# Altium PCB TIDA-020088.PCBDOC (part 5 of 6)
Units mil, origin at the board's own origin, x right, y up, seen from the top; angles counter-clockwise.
Board outline 7520.69 x 5119.11 mil, 6 copper layers (TOP, GND02, SIG03, SIG04, GND05, BOTTOM), stack 87.024 mil thick; 539 components, 269 nets, 1479 pads, 2085 vias.
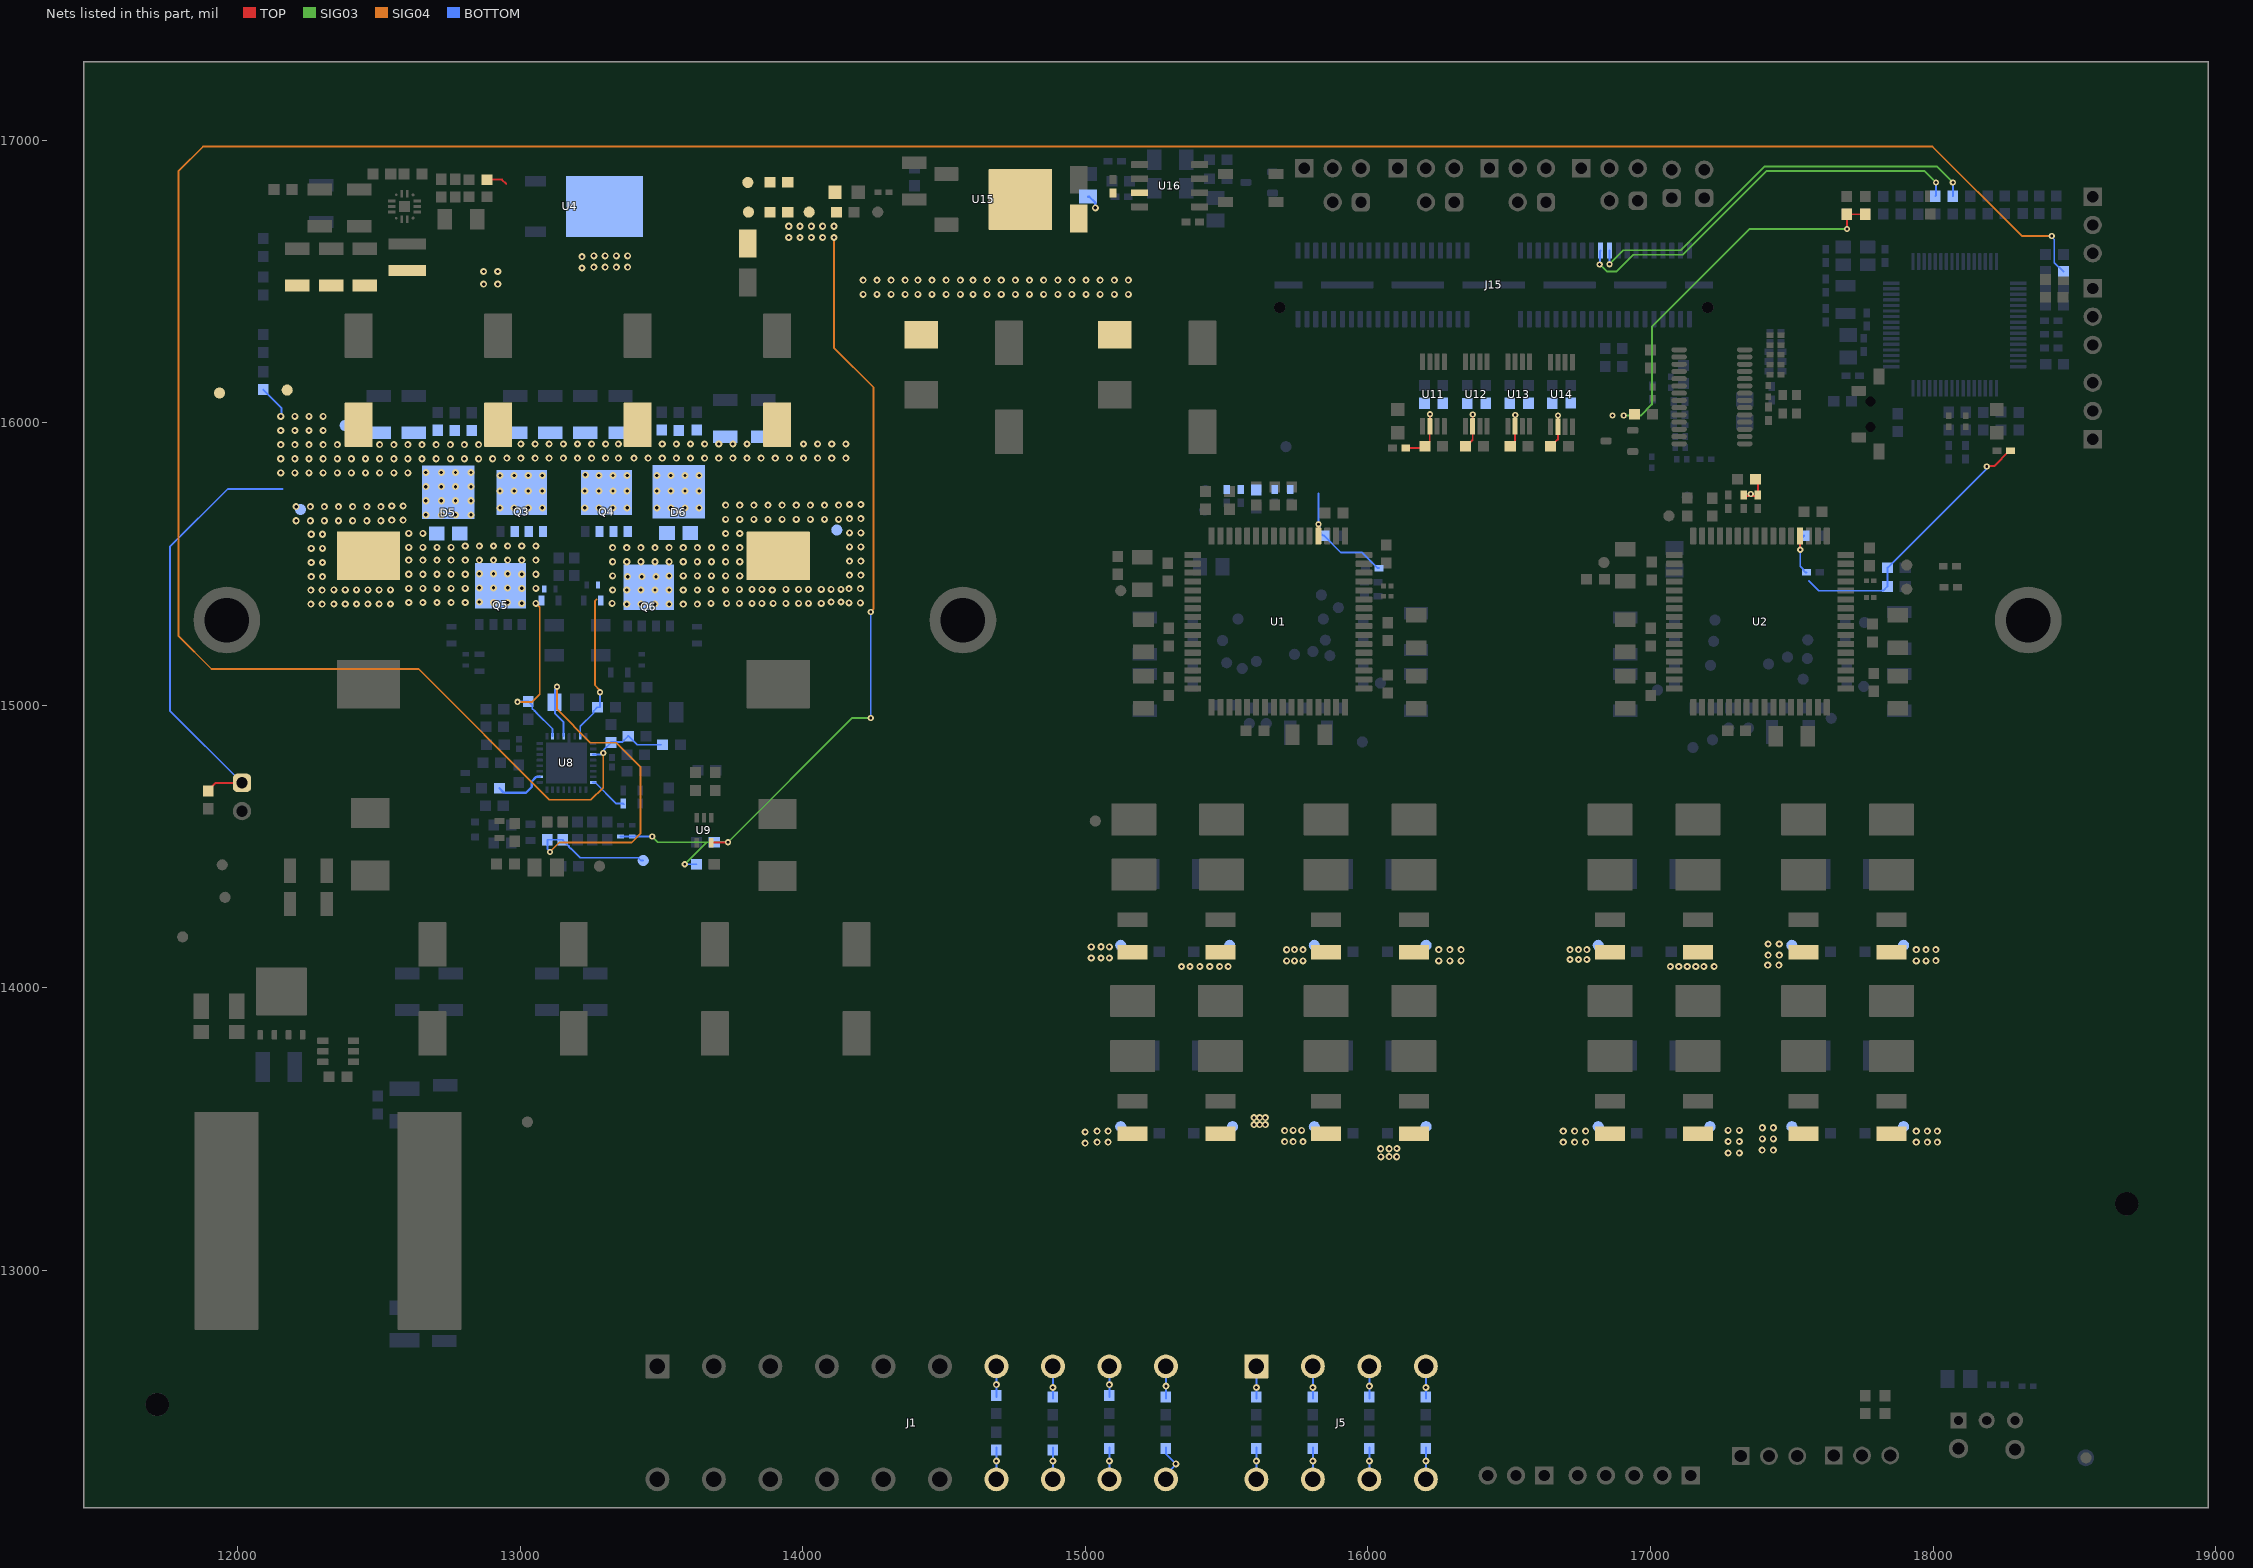
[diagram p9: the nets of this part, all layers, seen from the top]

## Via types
v1: diameter 25, hole 12, TOP to BOTTOM, tented both sides, 1621 vias
v2: diameter 22, hole 10, TOP to BOTTOM, tented both sides, 436 vias
v3: diameter 236.22, hole 137.8, TOP to BOTTOM, 15 vias
v4: diameter 19.68, hole 7.87, TOP to BOTTOM, tented both sides, 12 vias
v5: diameter 19.68, hole 7.87, TOP to BOTTOM, 1 vias

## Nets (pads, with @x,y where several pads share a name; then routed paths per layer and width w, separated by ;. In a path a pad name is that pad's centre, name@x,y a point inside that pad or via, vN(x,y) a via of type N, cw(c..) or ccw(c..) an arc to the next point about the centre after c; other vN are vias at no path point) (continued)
SPK_OUT1+: C23.1 C27.1 J1.14 R2.2 TP8.1 | length 113.4
  BOTTOM w6.5: J1.14@14685,12260 v1(14685,12325) C27.1@14685,12373.43
  other v1: 15596.62,13515.39 15616.62,13515.39 15636.62,13515.39 15596.62,13540.39 15616.62,13540.39 15636.62,13540.39
SPK_OUT1-: C24.1 C28.1 J1.13 R4.2 TP10.1 | length 113.4
  BOTTOM w6.5: C28.1@14685,12551.57 v1(14685,12595) ; v1@14685,12590 J1.13@14685,12660
  other v1: 14999.23,13449.87 15041.24,13453.2 15080.61,13453.2 14999.23,13489.24 15041.24,13492.57 15080.61,13492.57
SPK_OUT2+: C31.1 C35.1 J1.16 R8.2 TP14.1 | length 113.4
  BOTTOM w6.5: J1.16@14885,12260 v1(14885,12325) C35.1@14885,12373.43
  other v1: 15340,14075 15370,14075 15405,14075 15440,14075 15475,14075 15505,14075
SPK_OUT2-: C32.1 C36.1 J1.15 R10.2 TP16.1 | length 113.4
  BOTTOM w6.5: C36.1@14885,12546.57 v1(14885,12585) J1.15@14885,12660
  other v1: 15020.63,14105 15055,14105 15085,14105 15020.63,14144.37 15085,14144.37 15055,14145
SPK_OUT3+: C39.1 C43.1 J1.18 R12.2 TP20.1 | length 113.4
  BOTTOM w6.5: J1.18@15085,12260 v1(15085,12325) C43.1@15085,12373.43
  other v1: 16250.61,14095.2 16289.98,14095.2 16329.98,14095.2 16250.61,14134.57 16289.98,14134.57 16329.98,14134.57
SPK_OUT3-: C40.1 C44.1 J1.17 R13.2 TP22.1 | length 113.4
  BOTTOM w6.5: C44.1@15085,12551.57 v1(15085,12595) ; v1@15085,12590 J1.17@15085,12660
  other v1: 15712.14,14094.9 15740,14095 15770,14095 15712.14,14134.27 15740,14135 15770,14135
SPK_OUT4+: C47.1 C51.1 J1.20 R14.2 TP26.1 | length 142.4
  BOTTOM w6.5: J1.20@15285,12260 15285,12275.94 15320,12310.94 v1(15320,12315) 15285,12350 C51.1@15285,12373.43
  other v1: 16045.69,13401.25 16074.71,13402 16101.74,13401.75 16045,13430 16075,13430 16101.99,13431.02
SPK_OUT4-: C48.1 C52.1 J1.19 R17.2 TP28.1 | length 113.4
  BOTTOM w6.5: C52.1@15285,12546.57 v1(15285,12590) J1.19@15285,12660
  other v1: 15705,13455 15735,13455 15770,13455 15705,13494.37 15735,13495 15765,13495
SPK_OUT5+: C75.1 C79.1 J5.2 R21.2 TP37.1 | length 113.4
  BOTTOM w6.5: J5.2@15605,12260 v1(15605,12325) C79.1@15605,12373.43
  other v1: 17275,13415 17314.37,13415 17275,13455.63 17314.37,13455.63 17275,13495 17314.37,13495
SPK_OUT5-: C76.1 C80.1 J5.1 R23.2 TP39.1 | length 113.4
  BOTTOM w6.5: C80.1@15605,12546.57 v1(15605,12585) J5.1@15605,12660
  other v1: 16691.24,13453.2 16731.24,13453.2 16770.61,13453.2 16691.24,13492.57 16731.24,13492.57 16770.61,13492.57
SPK_OUT6+: C83.1 C87.1 J5.4 R27.2 TP43.1 | length 113.4
  BOTTOM w6.5: J5.4@15805,12260 v1(15805,12325) C87.1@15805,12373.43
  other v1: 17070,14075 17100,14075 17130,14075 17160,14075 17189,14074.99 17225,14075
SPK_OUT6-: C84.1 C88.1 J5.3 R28.2 TP45.1 | length 113.4
  BOTTOM w6.5: C88.1@15805,12546.57 v1(15805,12585) J5.3@15805,12660
  other v1: 16715,14100 16745,14100 16775,14100 16715,14135 16745,14135 16775,14135
SPK_OUT7+: C91.1 C95.1 J5.6 R30.2 TP49.1 | length 113.4
  BOTTOM w6.5: J5.6@16005,12260 v1(16005,12325) C95.1@16005,12373.43
  other v1: 17940.61,14095.2 17975,14095 18010,14095.63 17940.61,14134.57 17975,14135 18010,14135
SPK_OUT7-: C92.1 C96.1 J5.5 R31.2 TP51.1 | length 113.4
  BOTTOM w6.5: C96.1@16005,12546.57 J5.5@16005,12660
  other v1: 16005,12590 17415,14080 17454.37,14080 17416.24,14115.2 17455.61,14115.2 17416.24,14154.57 17455.61,14154.57
SPK_OUT8+: C99.1 C103.1 J5.8 R32.2 TP55.1 | length 113.4
  BOTTOM w6.5: J5.8@16205,12260 v1(16205,12325) C103.1@16205,12373.43
  other v1: 17940.61,13453.2 17979.98,13453.2 18014.98,13453.2 17940.61,13492.57 17979.98,13492.57 18014.98,13492.57
SPK_OUT8-: C100.1 C104.1 J5.7 R33.2 TP57.1 | length 113.4
  BOTTOM w6.5: C104.1@16205,12546.57 v1(16205,12585) J5.7@16205,12660
  other v1: 17395,13425 17435,13425 17395.63,13465 17435,13465 17395.63,13504.37 17435,13504.37
SS: C195.1 U8.2 | length 184.1
  BOTTOM w8: C195.1@12926.16,14705.65 12940.86,14690.95 12945.58,14690.95 12946.53,14690 13020,14690 13040,14710 13040,14730 13055.5,14745.5 13067.75,14745.5 U8.2@13068.67,14746.42
SW1: C175.1 C179.1 D5.1 D5.2 L19.1 Q3.1 Q3.2 Q3.3 Q5.5 R75.1 TP79.1 U8.10 | length 601.3
  SIG04 w6.5: v2(12989.89,15011.7) 13041.7,15011.7 13069,15039 13069,15346 13065,15350
  BOTTOM w6.5: C179.1@13028.49,15013.2 13042.23,14999.45 13042.23,14987.77 13050.36,14979.64 13051.23,14979.64 13056.94,14973.93 13056.94,14973.06 13113.95,14916.05 U8.10@13113.95,14890.12
  BOTTOM w8: v2(12989.89,15011.7) 13026.99,15011.7 C179.1@13028.49,15013.2
  other v1: 12258.39,15357.32 12298.39,15357.32 12340.35,15357.95 12380.35,15357.95 12420.35,15357.95 12460.35,15357.95 12500.35,15357.95 12540.35,15357.95 13005,15360 13055,15360 12605.11,15363.31 12655.11,15363.31 12705.11,15363.31 12755.11,15363.31 12805.11,15363.31 12905.11,15363.31 12955.11,15363.31 12855,15365 12258.39,15407.32 12298.39,15407.32 12340.35,15407.95 12380.35,15407.95 12420.35,15407.95 12460.35,15407.95 12500.35,15407.95 12540.35,15407.95 12605.11,15413.31 12655.11,15413.31 12705.11,15413.31 12755.11,15413.31 12805.11,15413.31 13005.11,15413.31 13055.11,15413.31 12855,15415 12905,15415 12955,15415 12260,15455 12300,15455 12605.11,15463.31 12655.11,15463.31 12705.11,15463.31 12755.11,15463.31 12805.11,15463.31 13005.11,15463.31 13055.11,15463.31 12855,15465 12905,15465 12955,15465 12260,15505 12300,15505 12605.11,15513.31 12655.11,15513.31 12705.11,15513.31 12755.11,15513.31 12805.11,15513.31 12855.11,15513.31 12905.11,15513.31 12955.11,15513.31 13005.11,15513.31 13055.11,15513.31 12260,15555 12300,15555 12605.11,15558.31 12655.11,15558.31 12705.11,15558.31 12755.11,15558.31 12805.11,15563.31 12855.11,15563.31 12905.11,15563.31 12955.11,15563.31 13005.11,15563.31 13055.11,15563.31 12260,15605 12300,15605 12605.11,15608.31 12655.11,15608.31 12206.61,15652.68 12256.61,15652.68 12306.61,15652.68 12356.61,15652.68 12406.61,15652.68 12456.61,15652.68 12506.61,15652.68 12545,15655 12585,15655 12206.61,15702.68 12256.61,15702.68 12306.61,15702.68 12356.61,15702.68 12406.61,15702.68 12456.61,15702.68 12506.61,15702.68 12545,15705 12585,15705
SW2: C176.1 C180.2 D6.1 D6.2 L20.2 Q4.1 Q4.2 Q4.3 Q6.5 R76.1 TP80.1 U8.15 | length 529.6
  SIG04 w6.5: 13270,15375 13264.2,15369.2 13264.2,15071.16 13280.11,15055.25 13280.11,15047.83 v2(13282.41,15045.54)
  BOTTOM w6.5: U8.15@13212.45,14890.2 U8.15@13212.37,14890.12 13212.37,14925.38 13259.02,14972.04 13259.02,14979.14 13272.72,14992.84 C180.2@13273.71,14992.84 13282.41,14992.84 v2(13282.41,15045.54)
  other v1: 13376.61,15357.68 13426.61,15357.68 13476.61,15357.68 13526.61,15357.68 13576.61,15357.68 13626.61,15357.68 13325,15360 13675,15360 13730,15360 13775,15360 13820,15360 13855,15360 13895,15360 13940,15360 13985,15360 14020,15360 14065,15360 14163.39,15362.32 14203.39,15362.32 14100,15365 14135,15365 13326.61,15407.68 13376.61,15407.68 13426.61,15407.68 13476.61,15407.68 13526.61,15407.68 13576.61,15407.68 13626.61,15407.68 13726.61,15407.68 13891.61,15407.68 13675,15410 13775,15410 13820,15410 13855,15410 13940,15410 13985,15410 14020,15410 14065,15410 14100,15410 14135,15410 14163.39,15412.32 14203.39,15412.32 13380,15455 13430,15455 13480,15455 13326.61,15457.68 13526.61,15457.68 13576.61,15457.68 13626.61,15457.68 13676.61,15457.68 13726.61,15457.68 13776.61,15457.68 14165,15460 14205,15460 13326.61,15507.68 13376.61,15507.68 13426.61,15507.68 13476.61,15507.68 13526.61,15507.68 13576.61,15507.68 13626.61,15507.68 13676.61,15507.68 13726.61,15507.68 13776.61,15507.68 14165,15510 14205,15510 13326.61,15557.68 13376.61,15557.68 13426.61,15557.68 13476.61,15557.68 13526.61,15557.68 13576.61,15557.68 13626.61,15557.68 13676.61,15557.68 13726.61,15557.68 13776.61,15557.68 14165,15560 14205,15560 13726.61,15607.68 13776.61,15607.68 14165,15610 14205,15610 13726.61,15657.68 13776.61,15657.68 13826.61,15657.68 13876.61,15657.68 13926.61,15657.68 13976.61,15657.68 14026.61,15657.68 14076.61,15657.68 14126.61,15657.68 14165,15660 14205,15660 13726.61,15707.68 13776.61,15707.68 13826.61,15707.68 13876.61,15707.68 13926.61,15707.68 13976.61,15707.68 14026.61,15707.68 14076.61,15707.68 14126.61,15707.68 14165,15710 14205,15710
SYNCIN: R98.2 U8.24 | length 140
  BOTTOM w6.5: U8.24@13257.65,14726.73 13264.38,14726.73 13339.33,14651.78 R98.2@13363.97,14651.78 ; R98.2@13363.97,14649.37 R98.2@13366.63,14649.37
UART_RX: J15.62 R167.1 | length 1479.8
  SIG03 w6.5: v2(16854.44,16560.56) 16903.89,16610 17107.37,16610 17404.37,16907 18013,16907 v2(18070,16850)
  BOTTOM w6.5: v2(16854.44,16560.56) 16854.54,16560.65 16854.54,16608.82 J15.62@16854.64,16608.92 ; v2(18070,16850) 18070,16801.44 R167.1@18070.1,16801.35
UART_TX: J15.60 R166.1 | length 1464.6
  SIG03 w6.5: v2(16820,16560) 16845,16535 16880,16535 16939,16594 17114,16594 17411,16891 17969,16891 v2(18010,16850)
  BOTTOM w6.5: v2(16820,16560) 16821.57,16561.57 16821.57,16607.35 J15.60@16823.14,16608.92 ; R166.1@18008.33,16801.07 18010,16802.73 v2(18010,16850)
UVLO/EN: C181.1 R64.1 R94.2 R146.2 U8.19 | length 10746.7
  SIG04 w6.5: v2(13293.25,14830.44) 13293.25,14708.25 13250,14665 13102.73,14665 12639.73,15128 11907,15128 11790,15245 11790,16890 11877,16977 17998,16977 18315,16660 v2(18420,16660)
  BOTTOM w6.5: U8.19@13257.65,14825.16 v2@13284.72,14825.16 ; v2@13293.25,14832.49 v2(13293.25,14830.44) 13295.55,14832.74 13295.55,14842.04 13320.93,14867.42 R94.2@13320.93,14868.4 ; R94.2@13320.93,14869.39 13361.09,14869.39 13367.41,14875.7 13367.41,14876.69 13381.11,14890.39 13383.08,14890.39 13413.47,14860 C181.1@13498.5,14860 ; v2(18420,16660) 18420,16657.33 18429.19,16648.14 18429.19,16566.32 18460.51,16535 R146.2@18461.5,16535
VCC: C4.2 C56.2 C193.1 C208.2 C209.2 C210.2 C211.2 C212.2 C213.2 C214.2 C215.2 D3.1 L14.2 L16.2 L17.1 L18.2 R5.2 R6.2 R7.2 R11.2 R15.2 R16.2 R18.1 R24.2 R25.2 R26.2 R29.2 R35.1 R60.2 R61.2 R99.2 R100.2 R104.2 R155.1 R160.1 R163.1 R169.1 R171.1 R173.1 TP69.1 U1.4 U2.4 U9.5 U11.6 U12.6 U13.6 U14.6 | length 6733.3
  TOP w6.5: U9.5@13675.59,14513.23 13676.48,14514.11 13734.11,14514.11 v2(13735,14515) ; U1.4@15824.63,15598.41 U1.4@15824.25,15598.78 15824.63,15599.15 15824.63,15639.63 v2(15825,15640) ; R171.1@16133.62,15910 16133.77,15910.15 16195.34,15910.15 R155.1@16201.28,15916.08 16202.26,15916.08 16215.96,15929.78 16215.96,15930.77 16218.82,15933.63 U11.6@16218.82,15986.65 16219.13,15986.97 16219.13,16029.52 v2(16219.45,16029.84) ; R160.1@16345.39,15915.78 16346.37,15915.78 16370.59,15940 U12.6@16370.59,15986.65 16370.85,15986.91 16370.85,16028.02 v2(16371.1,16028.27) ; R163.1@16503.39,15916.39 16504.37,15916.39 16518.07,15930.09 16518.07,15931.08 16520.59,15933.59 U13.6@16520.59,15986.65 16520.92,15986.98 16520.92,16026.49 v2(16521.24,16026.81) ; R169.1@16646.32,15915.71 16647.3,15915.71 16672.2,15940.62 U14.6@16672.2,15985.83 v2(16672.21,16025.44) ; R25.2@17330,15743.62 17333.62,15740 v2@17355,15740 ; v2(17355,15747) v2@17355,15740 ; R35.1@17371.5,15800 17380,15791.5 R26.2@17380,15743.62 17376.38,15740 v2@17355,15740 ; U2.4@17529.25,15598.78 17529.63,15598.41 17529.63,15550.37 v2(17530,15550) ; v2(17695,16685) R60.2@17695,16737.4 R61.2@17760,16737.4 ; v2(18190,15845) 18191.32,15846.32 18216,15846.32 18269.68,15900 R173.1@18273.62,15900 R173.1@18275,15898.62
  SIG03 w6.5: v2(13466.73,14535) 13486.73,14515 13659.5,14515 ; v2(13581.63,14437.13) 13659.5,14515 ; v2(14240,14955) 14175,14955 v2(13735,14515) 13659.5,14515 ; v2(16905,16025) 16965.3,16025 17005,16064.7 17005,16340 17350,16685 v2(17695,16685)
  SIG04 w6.5: v1(14110,16655) 14110,16265 14250,16125 14250,15340 v2(14240,15330)
  BOTTOM w6.5: R104.2@13355,14535 R99.2@13396,14535 v2(13466.73,14535) ; v2(13581.63,14437.13) R100.2@13623.48,14437.13 ; C193.1@13686.5,14515 v2(13735,14515) ; v2(14240,14955) v2(14240,15330) ; 15825,15750 v2(15825,15640) 15825,15636.75 15828.82,15632.93 15828.82,15613.7 15842.52,15600 15844.49,15600 15904.49,15540 15979.68,15540 16034.68,15485 R5.2@16038.62,15485 ; C56.2@17543.5,15600 17530,15586.5 v2(17530,15550) 17530,15491.86 17541.11,15480.75 17541.11,15476.81 17547.92,15470 R24.2@17551.86,15470 ; 17560,15440 17595,15405 17817.96,15405 17819.26,15406.3 17824.8,15406.3 R29.2@17838.5,15420 R11.2@17838.52,15486.7 17839.5,15486.7 18187.7,15834.9 18187.7,15842.7 v2(18190,15845)
  other v1: 13950,16655 13990,16655 14030,16655 14070,16655 13950,16695 13990,16695 14030,16695 14070,16695 14110,16695
  other v2: 16865,16025
VCC_B: C189.1 R97.1 R115.2 TP83.1 U8.12 | length 1650.4
  SIG04 w6.5: v2(13105.01,14480.5) 13138.41,14513.9 13393.9,14513.9 13425,14545 13425,14781.38 13339.44,14866.94 13248.06,14866.94 13130,14985 v2(13130,15065.14)
  BOTTOM w6.5: v2(13105.01,14480.5) 13105.01,14482.52 13095.63,14491.9 R97.1@13095.63,14523.5 R115.2@13150.63,14523.5 ; v2(13130,15065.14) 13130,15061.89 13123.23,15055.12 13123.23,15010 13123.23,14969.41 13153.32,14939.32 U8.12@13153.32,14890.12 ; R115.2@13150.63,14522.52 13171.93,14501.22 13171.93,14499.18 13178.8,14492.32 13179.5,14492.32 13211.62,14460.2 13230.94,14460.2 13231.15,14460 13417.05,14460 13427.05,14450 TP83.1@13435,14450
VCC_BUCK: C123.1 C124.1 C125.1 L15.2 L16.1 R38.2 TP71.1 | length 74.7
  TOP w6.5: R38.2@12881.5,16860 12935,16860 12950,16845
  other v1: 12870,16490 12920,16490 12870,16535 12920,16535
VCC_LDO: C106.1 L14.1 TP68.1 U4.4
  other v1: 13218.35,16547.32 13260,16550 13300,16550 13340,16550 13380,16550 13218.35,16587.32 13260,16590 13300,16590 13340,16590 13380,16590
VCC_LDO_5V: C114.1 C154.2 C172.1 U15.4 U16.3 | length 53.7
  BOTTOM w8: C154.2@15008.74,16799.7 15014,16799.7 15035,16778.7 v1(15035,16760)
VOUT: C141.1 C142.1 C144.1 C145.1 C146.1 C147.1 C148.1 C149.1 C150.1 C151.1 C152.1 C153.1 C161.1 C162.1 C163.1 C166.1 C167.1 C168.1 C169.1 C170.1 D5.3 D6.3 J7.1 J8.1 J9.1 Q3.5 Q4.5 R49.1 R83.1 TP73.1 TP74.1 TP75.1 | length 1678.7
  TOP w6.5: R83.1@11895,14696.5 11895,14697.48 11922.52,14725 J9.1@12015,14725
  BOTTOM w6.5: J9.1@12015,14725 11760,14980 11760,15560 11965,15765 12157.78,15765 ; R49.1@12090,16117.01 12090,16116.02 12155,16051.02 12155,16024.94 v1(12152.19,16022.13)
  other v1: 12665.5,15673.5 12720.5,15673.5 12770.5,15673.5 12825.5,15673.5 12928,15698 12978,15698 13028,15698 13078,15698 13228,15698 13278,15698 13328,15698 13378,15698 13483,15698 13533,15698 13583,15698 13633,15698 12665.5,15723.5 12720.5,15723.5 12770.5,15723.5 12825.5,15723.5 12928,15758 12978,15758 13028,15758 13078,15758 13228,15758 13278,15758 13328,15758 13378,15758 13483,15758 13533,15758 13583,15758 13633,15758 12665.5,15773.5 12720.5,15773.5 12770.5,15773.5 12825.5,15773.5 12928,15813 12978,15813 13028,15813 13078,15813 13278,15813 13328,15813 13378,15813 13483,15813 13533,15813 13583,15813 13633,15813 13230,15815 12152.19,15822.13 12202.19,15822.13 12252.19,15822.13 12302.19,15822.13 12352.19,15822.13 12402.19,15822.13 12452.19,15822.13 12502.19,15822.13 12552.19,15822.13 12602.19,15822.13 12665.5,15823.5 12720.5,15823.5 12770.5,15823.5 12825.5,15823.5 12152.19,15872.13 12202.19,15872.13 12252.19,15872.13 12302.19,15872.13 12352.19,15872.13 12402.19,15872.13 12452.19,15872.13 12502.19,15872.13 12552.19,15872.13 12602.19,15872.13 12652.19,15872.13 12702.19,15872.13 12752.19,15872.13 12802.19,15872.13 12852.19,15872.13 12902.19,15872.13 12952.19,15874.13 13002.19,15874.13 13052.19,15874.13 13102.19,15874.13 13152.19,15874.13 13202.19,15874.13 13252.19,15874.13 13302.19,15874.13 13347.19,15874.13 13402.19,15874.13 13452.19,15874.13 13502.19,15874.13 13552.19,15874.13 13602.19,15874.13 13652.19,15874.13 13702.19,15874.13 13752.19,15874.13 13802.19,15874.13 13852.19,15874.13 13902.19,15874.13 13952.19,15874.13 14002.19,15874.13 14052.19,15874.13 14102.19,15874.13 14152.19,15874.13 12152.19,15922.13 12202.19,15922.13 12252.19,15922.13 12302.19,15922.13 12352.19,15922.13 12502.19,15922.13 12552.19,15922.13 12602.19,15922.13 12652.19,15922.13 12702.19,15922.13 12752.19,15922.13 12802.19,15922.13 12852.19,15922.13 13002.19,15924.13 13052.19,15924.13 13102.19,15924.13 13152.19,15924.13 13202.19,15924.13 13252.19,15924.13 13302.19,15924.13 13347.19,15924.13 13502.19,15924.13 13552.19,15924.13 13602.19,15924.13 13652.19,15924.13 13702.19,15924.13 13752.19,15924.13 13802.19,15924.13 14002.19,15924.13 14052.19,15924.13 14102.19,15924.13 14152.19,15924.13 12152.19,15972.13 12202.19,15972.13 12252.19,15972.13 12302.19,15972.13 12202.19,16022.13 12252.19,16022.13 12302.19,16022.13 14213.5,16454.13 14262.19,16454.13 14312.19,16454.13 14362.19,16454.13 14407.19,16454.13 14457.19,16454.13 14507.19,16454.13 14557.19,16454.13 14602.19,16454.13 14652.19,16454.13 14702.19,16454.13 14752.19,16454.13 14802.19,16454.13 14852.19,16454.13 14902.19,16454.13 14952.19,16454.13 15002.19,16454.13 15052.19,16454.13 15102.19,16454.13 15152.19,16454.13 14213.5,16504.13 14262.19,16504.13 14312.19,16504.13 14362.19,16504.13 14407.19,16504.13 14457.19,16504.13 14507.19,16504.13 14557.19,16504.13 14602.19,16504.13 14652.19,16504.13 14702.19,16504.13 14752.19,16504.13 14802.19,16504.13 14852.19,16504.13 14902.19,16504.13 14952.19,16504.13 15002.19,16504.13 15052.19,16504.13 15102.19,16504.13 15152.19,16504.13
pads on no net: J15. J15.1 J15.3 J15.5 J15.9 J15.11 J15.13 J15.14 J15.17 J15.19 J15.21 J15.23 J15.24 J15.28 J15.30 J15.32 J15.33 J15.34 J15.38 J15.40 J15.41 J15.42 J15.43 J15.44 J15.47 J15.48 J15.51 J15.52 J15.53 J15.54 J15.55 J15.56 J15.59 J15.61 J15.63 J15.64 J15.67 J15.68 J15.69 J15.70 J15.71 J15.72 J15.73 J15.74 J15.77 J15.78 J15.79 J15.80 Q1.9@12096.53,13937.36 Q1.9@12096.53,14003.5 Q1.9@12154.41,13937.36 Q1.9@12154.41,14003.5 Q1.9@12212.28,13937.36 Q1.9@12212.28,14003.5 S1. U1.58 U2.58 U5.2 U5.4 U5.5 U5.8 U5.9 U5.12 U5.14 U7.1 U7.2 U7.3 U7.4 U7.9 U7.15 U7.16 U7.17 U7.18 U10.7 U10.10 U10.16 U10.17 U10.18 U10.19 U10.21 U10.22 U10.23 U10.27 U10.28 U10.29 U10.30 U10.31 U10.35 U10.36 U10.37 U10.39 U10.49 U10.54 U10.55 U10.59 U11.5 U11.7 U11.8 U12.5 U12.7 U12.8 U13.5 U13.7 U13.8 U14.5 U14.7 U14.8

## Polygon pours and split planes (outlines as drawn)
no net on Top Solder "Top Solder-No Net" (solid): 31 vertices, not listed, extent 11474.56,12180 18954,17254.71
no net on Top Solder "NONET_L06_P-001" (solid): 12652.62,15655.93 13649.21,15655.93 13660,15666.71 13660,15830 13650.33,15839.67 12654.67,15839.67 12643.54,15828.54 12643.54,15665.01
no net on Top Solder "NONET_L06_P-001" (solid): 13310.61,15340.72 13635.72,15340.72 13645,15350 13645,15575 13633.51,15586.49 13308.47,15586.49 13301.52,15579.54 13301.52,15349.81
no net on Top Solder "NONET_L06_P-001" (solid): 12746.45,15343.55 13066.55,15343.55 13075,15352 13075,15580 13065.68,15589.31 12744.32,15589.32 12737.37,15582.37 12737.37,15352.63
GND on GND05 "GND_L05_P1536" (solid, remove dead copper, pour order 1536): 11452.13,17275.99 18969.7,17275.99 18969.7,12161.27 11452.13,12161.27
GND on BOTTOM "BOTTOM-GND" (solid, pour order 1194): 132 vertices, not listed, extent 11452.06,12202.77 18931.5,17277.48
BIAS on BOTTOM "BIAS_L06_P1211" (solid, pour order 1211): 12355,13985 13385,13985 13410,14010 13410,14345 13395,14360 12565,14360 12540,14385 12540,14435 12515,14460 12350,14460 12335,14445 12335,14005
NETC105_1 on BOTTOM "NETC105_1_L06_P1545" (solid, pour order 1545): 11815,13785 11830,13800 12125,13800 12140,13785 12140,13660 12125,13645 11830,13645 11815,13660
SPK_OUT8+ on BOTTOM "SPK_OUT8+_L06_P1472" (solid, pour order 1472): 18035.95,13427.29 17822.71,13427.29 17802.72,13447.28 17802.72,13530.54 17822.72,13550.54 18034.46,13550.54 18055,13530 18055,13446.34
BAT_IN on BOTTOM "BAT_IN_L06_P1195" (solid, pour order 1195): 14510,12475 13385,12475 13335,12525 13335,12755 13280,12810 12380,12810 12330,12860 12330,13520 12385,13575 14500,13575 14560,13515 14560,12525
NetC139_1 on BOTTOM "NETC139_1_L06_P1539" (solid, pour order 1539): 14345,16780 14345,16850 14360,16865 14425,16865 14430,16860 14430,16820 14465,16785 14585,16785 14595,16775 14595,16755 14586.18,16746.18 14378.82,16746.18
BIAS on BOTTOM "BIAS_L06_P1537" (solid, remove dead copper, pour order 1537): 14240,16945 14260,16965 14410,16965 14435,16940 14435,16895 14412.33,16872.33 14347.33,16872.33 14330,16855 14255,16855 14240,16870 14240,16910
GND on BOTTOM "GND_L06_P1540" (solid, remove dead copper, pour order 1540): 11450,17280 18967.57,17280 18967.57,12165.28 11450,12165.28
PVDD_2 on BOTTOM "PVDD_2_L06_P1530" (solid, pour order 1530): 17730.89,15365.89 17745.23,15380.23 17924.77,15380.23 17950,15355 17950,15295 17935,15280 17835.51,15280 17795.51,15320 17739.04,15320 17730.89,15328.15
GND on BOTTOM "GND_L06_P1528" (solid, pour order 1528): 17754.38,15120.63 17754.38,15200.63 17778.75,15225 17970.01,15225 17994.38,15200.63 17994.38,15120.63 17953.75,15080 17795.01,15080
PVDD_2 on BOTTOM "PVDD_2_L06_P1527" (solid, pour order 1527): 17850.63,15030.62 17930.63,15030.62 17950.63,15010.62 17950.63,14810.62 17930.63,14790.62 17850.63,14790.62 17825.63,14815.62 17825.63,15005.62
GND on BOTTOM "GND_L06_P1526" (solid, pour order 1526): 17030,15195 17030,15105 16992.56,15067.56 16807.44,15067.56 16770,15105 16770,15205 16790,15225 17000,15225
PVDD_2 on BOTTOM "PVDD_2_L06_P1525" (solid, pour order 1525): 17015,15360 17015,15265 16995,15245 16795,15245 16775,15265 16775,15365 16795,15385 16990,15385
GND on BOTTOM "GND_L06_P1524" (solid, pour order 1524): 17528.61,14960.14 17579.86,14960.14 17610,14930 17610,14751.52 17578.61,14720.14 17528.61,14720.14 17503.61,14745.14 17503.61,14935.14
PVDD_2 on BOTTOM "PVDD_2_L06_P1523" (solid, pour order 1523): 17398.61,14955.14 17478.61,14955.14 17498.61,14935.14 17498.61,14735.14 17478.61,14715.14 17398.61,14715.14 17373.61,14740.14 17373.61,14930.14
GND on BOTTOM "GND_L06_P1522" (solid, pour order 1522): 15838.61,14950.14 15918.61,14950.14 15938.61,14930.14 15938.61,14730.14 15918.61,14710.14 15838.61,14710.14 15813.61,14735.14 15813.61,14925.14
PVDD_1 on BOTTOM "PVDD_1_L06_P1521" (solid, pour order 1521): 15698.61,14950.14 15778.61,14950.14 15798.61,14930.14 15798.61,14730.14 15778.61,14710.14 15698.61,14710.14 15673.61,14735.14 15673.61,14925.14
PVDD_1 on BOTTOM "PVDD_1_L06_P1520" (solid, pour order 1520): 16130.63,15045.62 16210.63,15045.62 16230.63,15025.62 16230.63,14825.62 16210.63,14805.62 16130.63,14805.62 16105.63,14830.62 16105.63,15020.62
GND on BOTTOM "GND_L06_P1519" (solid, pour order 1519): 16295,15195 16295,15115 16265,15085 16085,15085 16055,15115 16055,15195 16080,15220 16270,15220
PVDD_1 on BOTTOM "PVDD_1_L06_P1518" (solid, pour order 1518): 16260,15335 16260,15255 16250,15245 16030,15245 16020,15255 16020,15335 16045,15360 16235,15360
GND on BOTTOM "GND_L06_P1517" (solid, pour order 1517): 15020,15190 15125,15190 15153.99,15218.99 15311.01,15218.99 15330,15200 15330,15105 15285,15060 14990,15060 14965,15085 14965,15135 15000,15170
PVDD_2 on BOTTOM "PVDD_2_L06_P1516" (solid, pour order 1516): 17105,14990 17105,14895 17085,14875 16885,14875 16865,14895 16865,15000 16880,15015 17080,15015
PVDD_1 on BOTTOM "PVDD_1_L06_P1515" (solid, pour order 1515): 15395,14990 15395,14895 15375,14875 15175,14875 15155,14895 15155,14995 15175,15015 15370,15015
PVDD_1 on BOTTOM "PVDD_1_L06_P1514" (solid, pour order 1514): 15330,15340 15330,15260 15310,15240 15110,15240 15090,15260 15090,15340 15115,15365 15305,15365
VCC on BOTTOM "VCC_L06_P1509" (solid, pour order 1509): 16905,15550 16715,15740 16715,15770 16940,15770 16965,15745 16965,15610
VCC on BOTTOM "VCC_L06_P1503" (solid, pour order 1503): 15482.8,15797.8 15500,15815 15725,15815 15770,15860 15770,15975 16950,15975 16950,15740 15499.52,15740 15482.8,15756.72
SW1 on BOTTOM "SW1_L06_P1244" (solid, pour order 1244): 12190,15725 12600,15725 12625,15700 12625,15650 12635,15640 13091.54,15640 13100,15631.54 13100,15485 13100,15365 13085,15350 13070,15335 12210,15335 12175,15370 12175,15610 12175,15710
VCC on BOTTOM "VCC_L06_P1504" (solid, pour order 1504): 16950,15815 16980,15785 17560,15785 17575,15770 17575,15440 17560,15425 17305,15425 17210,15520 16935,15520 16905,15550 16905,15805 16915,15815
SPK_OUT6+ on BOTTOM "SPK_OUT6+_L06_P1500" (solid, pour order 1500): 17045,14080.29 17059.71,14095 17105.87,14095 17114.68,14103.81 17114.68,14159.68 17125,14170 17240,14170 17260,14150 17260,14035 17240,14015 17055,14015 17045,14025
NETC85_1 on BOTTOM "NETC85_1_L06_P1499" (solid, pour order 1499): 17146.43,14340 17153.34,14346.92 17153.34,14463.34 17165,14475 17265,14475 17280,14460 17280,14220 17265,14205 17084.33,14205 17067.52,14221.81 17067.52,14322.52 17085,14340
SPK_OUT7- on BOTTOM "SPK_OUT7-_L06_P1498" (solid, pour order 1498): 17585.21,14025 17401.71,14025 17379.12,14047.6 17379.12,14188.94 17406.14,14215.97 17576.58,14215.97 17596.08,14196.47 17596.08,14035.86
NETC101_1 on BOTTOM "NETC101_1_L06_P1497" (solid, pour order 1497): 17838.69,13631.31 17838.69,13814.76 17865.54,13841.6 18006.89,13841.6 18033.91,13814.58 18033.91,13628.91 18015,13610 17860,13610
NETC102_1 on BOTTOM "NETC102_1_L06_P1496" (solid, pour order 1496): 17360,13634.79 17360,13818.29 17382.6,13840.88 17523.94,13840.88 17550.97,13813.86 17550.97,13643.42 17531.47,13623.92 17370.86,13623.92
NETC77_1 on BOTTOM "NETC77_1_L06_P1495" (solid, pour order 1495): 17151.35,13634.16 17151.35,13809.16 17178.2,13836.01 17319.55,13836.01 17346.57,13808.98 17346.57,13638.55 17327.07,13619.05 17166.46,13619.05
NETC78_1 on BOTTOM "NETC78_1_L06_P1494" (solid, pour order 1494): 16670,13640 16670,13815 16696.85,13841.85 16838.19,13841.85 16865.22,13814.82 16865.22,13644.39 16845.72,13624.89 16685.11,13624.89
SPK_OUT6- on BOTTOM "SPK_OUT6-_L06_P1493" (solid, pour order 1493): 16889.12,14032.42 16722.64,14032.42 16692.77,14062.29 16692.77,14188.51 16719.8,14215.53 16890.23,14215.53 16909.73,14196.03 16909.73,14053.03
NETC86_1 on BOTTOM "NETC86_1_L06_P1492" (solid, pour order 1492): 16681.39,14284.85 16681.39,14451.33 16711.26,14481.2 16837.48,14481.2 16864.5,14454.18 16864.5,14283.74 16845,14264.24 16702,14264.24
NETC49_1 on BOTTOM "NETC49_1_L06_P1491" (solid, pour order 1491): 16148.06,13590.31 16148.06,13815.31 16163.06,13830.31 16286.97,13830.31 16299.29,13818 16299.29,13591.54 16283.06,13575.31 16163.06,13575.31
SPK_OUT4+ on BOTTOM "SPK_OUT4+_L06_P1490" (solid, pour order 1490): 16020,13440.43 16029.57,13450 16093.38,13450 16104.77,13461.39 16104.77,13524.77 16115,13535 16225,13535 16245,13515 16245,13395 16220,13370 16030,13370 16020,13380 16020,13430
SPK_OUT4- on BOTTOM "SPK_OUT4-_L06_P1489" (solid, pour order 1489): 15880,13430 15703.13,13430 15679.12,13454.01 15679.12,13536.67 15699.12,13556.67 15878.33,13556.67 15903.4,13531.6 15903.4,13453.4
NETC50_1 on BOTTOM "NETC50_1_L06_P1488" (solid, pour order 1488): 15710,13585 15710,13810 15725,13825 15848.91,13825 15861.23,13812.68 15861.23,13586.23 15845,13570 15725,13570
SPK_OUT3+ on BOTTOM "SPK_OUT3+_L06_P1487" (solid, pour order 1487): 16325,14045 16140,14045 16110.13,14074.87 16110.13,14201.09 16130.13,14221.09 16325.13,14221.09 16354.59,14191.63 16354.59,14074.59
SPK_OUT3- on BOTTOM "SPK_OUT3-_L06_P1486" (solid, pour order 1486): 15875,14030 15690,14030 15660.13,14059.87 15660.13,14186.09 15680.13,14206.09 15875.13,14206.09 15904.59,14176.63 15904.59,14059.59
SPK_OUT2+ on BOTTOM "SPK_OUT2+_L06_P1485" (solid, pour order 1485): 15412.2,14095.82 15421.43,14105.05 15421.43,14171.43 15440,14190 15540,14190 15550,14180 15550,14065 15530,14045 15330,14045 15310,14065 15310,14090 15315.82,14095.82
NETC41_1 on BOTTOM "NETC41_1_L06_P1484" (solid, pour order 1484): 16147.61,14323.28 16147.61,14469.77 16177.48,14499.63 16303.7,14499.63 16330.72,14472.61 16330.72,14325.17 16305.72,14300.17 16170.72,14300.17
NETC42_1 on BOTTOM "NETC42_1_L06_P1483" (solid, pour order 1483): 15677.2,14311.58 15677.2,14458.06 15707.07,14487.93 15833.29,14487.93 15860.31,14460.91 15860.31,14313.47 15835.31,14288.47 15700.31,14288.47
NETC33_1 on BOTTOM "NETC33_1_L06_P1482" (solid, pour order 1482): 15461.89,14318.11 15461.89,14464.59 15491.76,14494.46 15617.98,14494.46 15645,14467.44 15645,14320 15620,14295 15485,14295
NETC25_1 on BOTTOM "NETC25_1_L06_P1481" (solid, pour order 1481): 15462.89,13628.19 15462.89,13813.19 15492.76,13843.06 15678.03,13843.06 15688.58,13832.51 15688.58,13618.87 15668.3,13598.6 15492.49,13598.6
SPK_OUT1+ on BOTTOM "SPK_OUT1+_L06_P1480" (solid, pour order 1480): 15658.4,13420 15434.58,13420 15424.12,13430.45 15424.12,13556.67 15444.12,13576.67 15639.12,13576.67 15668.58,13547.21 15668.58,13430.18
SPK_OUT1- on BOTTOM "SPK_OUT1-_L06_P1479" (solid, pour order 1479): 15188.99,13385.59 15003.99,13385.59 14974.12,13415.45 14974.12,13541.67 14994.12,13561.67 15189.12,13561.67 15218.58,13532.21 15218.58,13415.18
NETC26_1 on BOTTOM "NETC26_1_L06_P1478" (solid, pour order 1478): 14950,13615 14950,13800 14979.87,13829.87 15165.13,13829.87 15175.68,13819.32 15175.68,13605.68 15155.41,13585.41 14979.59,13585.41
SPK_OUT2- on BOTTOM "SPK_OUT2-_L06_P1477" (solid, pour order 1477): 15190,14040 15005,14040 14975.13,14069.87 14975.13,14196.09 14995.13,14216.09 15190.13,14216.09 15219.59,14186.63 15219.59,14069.59
NETC34_1 on BOTTOM "NETC34_1_L06_P1476" (solid, pour order 1476): 15000,14260 15000,14445 15029.87,14474.87 15156.09,14474.87 15176.09,14454.87 15176.09,14259.87 15146.63,14230.41 15029.59,14230.41
NETC94_1 on BOTTOM "NETC94_1_L06_P1475" (solid, pour order 1475): 17536.14,14324.26 17395.74,14324.26 17370,14350 17370,14450 17394.26,14474.26 17531.14,14474.26 17551.14,14454.26 17551.14,14339.26
NETC93_1 on BOTTOM "NETC93_1_L06_P1474" (solid, pour order 1474): 17851.56,14472.8 18034.06,14472.8 18061.56,14445.3 18061.56,14342.8 18041.56,14322.8 17856.56,14322.8 17836.56,14342.8 17836.56,14457.8
SPK_OUT7+ on BOTTOM "SPK_OUT7+_L06_P1473" (solid, pour order 1473): 17816.56,14192.8 17999.06,14192.8 18026.56,14165.3 18026.56,14062.8 18006.56,14042.8 17821.56,14042.8 17801.56,14062.8 17801.56,14177.8
SPK_OUT8- on BOTTOM "SPK_OUT8-_L06_P1471" (solid, pour order 1471): 17580,13400 17397.5,13400 17370,13427.5 17370,13530 17390,13550 17575,13550 17595,13530 17595,13415
SPK_OUT5+ on BOTTOM "SPK_OUT5+_L06_P1470" (solid, pour order 1470): 17320,13400 17137.5,13400 17110,13427.5 17110,13530 17130,13550 17315,13550 17335,13530 17335,13415
SPK_OUT5- on BOTTOM "SPK_OUT5-_L06_P1469" (solid, pour order 1469): 16885,13405 16692.5,13405 16665,13432.5 16665,13535 16685,13555 16880,13555 16909.46,13525.54 16909.46,13429.46
VCC on BOTTOM "VCC_L06_P1314" (solid, pour order 1314): 16815,15985 16815,16090 16920,16090 16950,16060 16950,15945 16825,15820 16785,15860 16785,15955
VCC on BOTTOM "VCC_L06_P1313" (solid, pour order 1313): 18 vertices, not listed, extent 13935,15790 16825,16645
VCC on BOTTOM "VCC_L06_P1312" (solid, pour order 1312): 13920,16720 13940,16740 14115,16740 14135,16720 14135,16645 14115,16625 13940,16625 13920,16645 13920,16695
3V3 on BOTTOM "3V3_L06_P1311" (solid, pour order 1311): 14170.08,16740 17545,16740 17565,16720 17565,16480 17535,16450 17470,16450 17440,16480 17440,16635 17420,16655 14360,16655 14335,16630 14169.95,16630 14149.88,16650.24 14150.47,16720.55
PVDD_2 on BOTTOM "PVDD_2_L06_P1280" (solid, pour order 1280): 14995,16135 15030,16170 15165,16170 15220,16115 15565,16115 15635,16045 15635,15852.5 15607.5,15825 15017.5,15825 14995,15847.5
PVDD_1 on BOTTOM "PVDD_1_L06_P1279" (solid, pour order 1279): 14332.5,16132.5 14367.5,16167.5 14502.5,16167.5 14557.5,16112.5 14902.5,16112.5 14972.5,16042.5 14972.5,15850 14945,15822.5 14355,15822.5 14332.5,15845
VCC_LDO on BOTTOM "VCC_LDO_L06_P1269" (solid, pour order 1269): 13150,16870 13180,16900 13445,16900 13475,16870 13475,16550 13445,16520 13185,16520 13150,16555
NetC108_1 on BOTTOM "NETC108_1_L06_P1268" (solid, pour order 1268): 12170,16805 12170,16880 12190,16900 13100,16900 13120,16880 13120,16815 13100,16795 13080,16795 12180,16795
BIAS on BOTTOM "BIAS_L06_P1267" (solid, pour order 1267): 11815,16850 12145,16850 12155,16840 12155,16665 12120,16630 11810,16630 11785,16655 11785,16830 11805,16850
VOUT on BOTTOM "VOUT_L06_P1258" (solid, pour order 1258): 29 vertices, not listed, extent 12130,15650 15225,16542.21
SW2 on BOTTOM "SW2_L06_P1245" (solid, pour order 1245): 13725,15735 14220,15735 14235,15720 14235,15360 14210,15335 13645,15335 13290,15335 13260,15365 13260,15630 13270,15640 13675,15640 13700,15665 13700,15715
BIAS on BOTTOM "BIAS_L06_P1229" (solid, pour order 1229): 13385,14360 13770,14360 13800,14390 13800,14435 13810,14445 14015,14445 14025,14435 14025,14360 14040,14345 14380,14345 14395,14330 14395,14010 14370,13985 13385,13985
BIAS on TOP "BIAS_L01_P1215" (solid, pour order 1215): 19 vertices, not listed, extent 11765,13887.66 13410,14465
NETC105_1 on TOP "NETC105_1_L01_P1544" (solid, pour order 1544): 12209.56,13750.44 12329.56,13750.44 12348.52,13731.48 12348.52,13658.52 12270,13580 12270,12800 12250,12780 12180,12780 12135,12825 12135,13765 12155,13785 12175,13785 12200,13760
NETC105_1 on TOP "NETC105_1_L01_P1543" (solid, pour order 1543): 11783.18,13873.18 12181.82,13873.18 12200,13855 12200,12800 12180,12780 11785,12780 11765,12800 11765,13855
GND on TOP "GND_L01_P1542" (solid, remove dead copper, pour order 1542): 11448.8,17280.82 18966.37,17280.82 18966.37,12166.09 11448.8,12166.09
VCC_LDO_5V on TOP "VCC_LDO_5V_L01_P1541" (solid, remove dead copper, pour order 1541): 19 vertices, not listed, extent 14645,16665 15233.07,16910
NetC139_1 on TOP "NETC139_1_L01_P1531" (solid, pour order 1531): 14355,16815 14435,16815 14465,16785 14585,16785 14595,16775 14595,16665.11 14584.89,16655 14360,16655 14340,16675 14340,16800
L2 on TOP "L2_L01_P1468" (solid, pour order 1468): 14145,14560 14165,14580 14165,14905 14120,14950 13685,14950 13660,14925 13660,14900 13735,14825 13735,14580 13755,14560
AGND on TOP "AGND_L01_P1508" (solid, pour order 1508): 13070,14855 13100,14885 13225,14885 13255,14855 13255,14730 13224.62,14699.62 13105.38,14699.62 13070,14735
SW1 on TOP "SW1_L01_P1223" (solid, pour order 1223): 12190,15725 12600,15725 12625,15700 12625,15650 12635,15640 13091.54,15640 13100,15631.54 13100,15485 13100,15365 13085,15350 13070,15335 12210,15335 12175,15370 12175,15610 12175,15710
GND on TOP "GND_L01_P1283" (solid, pour order 1283): 15361.93,15228.28 15411.72,15228.28 15420,15220 15420,15150 15411.66,15141.66 15411.66,15140.66 15345.66,15140.66 15335,15130 15335,15086.31 15313.69,15065 14985,15065 14965,15085 14965,15145 15015.86,15195.86 15094.13,15228.28
NETC30_1 on TOP "NETC30_1_L01_P1289" (solid, remove dead copper, pour order 1289): 25 vertices, not listed, extent 15085,14525 15525,15025
NETC86_1 on TOP "NETC86_1_L01_P1402" (solid, pour order 1402): 16691.81,14478.78 16936.22,14478.78 16950,14465 16950,14230 16927.94,14207.94 16689.23,14207.94 16673.21,14223.96 16673.21,14460.19
NETC101_1 on TOP "NETC101_1_L01_P1467" (solid, pour order 1467): 17778.52,13818.79 18020.1,13818.79 18040.94,13797.95 18040.94,13577.95 18010.94,13547.95 17775.94,13547.95 17759.93,13563.97 17759.93,13800.19
NETC102_1 on TOP "NETC102_1_L01_P1466" (solid, pour order 1466): 17388.52,13818.79 17630.1,13818.79 17650.94,13797.95 17650.94,13577.95 17620.94,13547.95 17385.94,13547.95 17369.93,13563.97 17369.93,13800.19
NETC77_1 on TOP "NETC77_1_L01_P1465" (solid, pour order 1465): 17092.58,13820.84 17334.16,13820.84 17355,13800 17355,13580 17325,13550 17090,13550 17073.98,13566.02 17073.98,13802.24
NETC78_1 on TOP "NETC78_1_L01_P1422" (solid, pour order 1422): 16687.58,13820.84 16929.16,13820.84 16950,13800 16950,13580 16920,13550 16685,13550 16668.98,13566.02 16668.98,13802.24
NETC42_1 on TOP "NETC42_1_L01_P1400" (solid, pour order 1400): 15693.6,14472.57 15912.43,14472.57 15935,14450 15935,14220 15916.73,14201.73 15698.27,14201.73 15675,14225 15675,14453.97
NETC41_1 on TOP "NETC41_1_L01_P1401" (solid, pour order 1401): 16086.18,14471.19 16288.81,14471.19 16310,14450 16310,14210 16300.35,14200.35 16083.6,14200.35 16067.58,14216.36 16067.58,14452.59
NETC33_1 on TOP "NETC33_1_L01_P1399" (solid, pour order 1399): 15392.37,14470 15625,14470 15645,14450 15645,14225 15619.16,14199.16 15389.79,14199.16 15373.77,14215.18 15373.77,14451.4
NETC71_2 on TOP "NETC71_2_L01_P1333" (solid, pour order 1333): 17086.07,14035.47 17324.53,14035.47 17340.49,14019.51 17340.49,13900.49 17325.47,13885.47 17089.9,13885.47 17067.47,13907.91 17067.47,14016.88
SPK_OUT2+ on TOP "SPK_OUT2+_L01_P1420" (solid, pour order 1420): 15343.92,14158.92 15556.08,14158.92 15575,14140 15575,14065 15560,14050 15335,14050 15322.5,14062.5 15322.5,14137.5
SPK_OUT1+ on TOP "SPK_OUT1+_L01_P1413" (solid, pour order 1413): 15409.93,13559.93 15637.99,13559.93 15657.5,13540.41 15657.5,13450 15632.5,13425 15410,13425 15388.79,13446.21 15388.79,13538.79
SPK_OUT4+ on TOP "SPK_OUT4+_L01_P1415" (solid, pour order 1415): 16037.27,13512.27 16242.73,13512.27 16257.8,13497.2 16257.8,13387.8 16250,13380 16035,13380 16024.57,13390.43 16024.57,13499.57
SPK_OUT6+ on TOP "SPK_OUT6+_L01_P1421" (solid, pour order 1421): 17064.55,14153.96 17231.04,14153.96 17249.66,14135.34 17249.66,14064.66 17230.05,14045.05 17064.66,14045.05 17045.96,14063.76 17045.96,14135.37
SPK_OUT8+ on TOP "SPK_OUT8+_L01_P1419" (solid, pour order 1419): 17789.89,13528.92 18021.08,13528.92 18040,13510 18040,13440 18026.14,13426.14 17783.86,13426.14 17771.29,13438.71 17771.29,13510.32
SPK_OUT8- on TOP "SPK_OUT8-_L01_P1418" (solid, pour order 1418): 17384.89,13528.92 17616.08,13528.92 17635,13510 17635,13415 17620.83,13400.83 17379.17,13400.83 17366.29,13413.71 17366.29,13510.32
SPK_OUT5+ on TOP "SPK_OUT5+_L01_P1417" (solid, pour order 1417): 17104.89,13528.92 17336.08,13528.92 17350,13515 17350,13415 17335,13400 17105,13400 17086.29,13418.71 17086.29,13510.32
SPK_OUT5- on TOP "SPK_OUT5-_L01_P1416" (solid, pour order 1416): 16664.89,13528.92 16896.08,13528.92 16915,13510 16915,13440 16895,13420 16665,13420 16646.29,13438.71 16646.29,13510.32
SPK_OUT4- on TOP "SPK_OUT4-_L01_P1414" (solid, pour order 1414): 15689.89,13538.92 15921.08,13538.92 15940,13520 15940,13450 15920,13430 15690,13430 15671.29,13448.71 15671.29,13520.32
SPK_OUT1- on TOP "SPK_OUT1-_L01_P1412" (solid, pour order 1412): 14964.89,13523.92 15243.73,13523.92 15261.29,13506.35 15261.29,13436.29 15240,13415 14965,13415 14946.29,13433.71 14946.29,13505.32
SPK_OUT7+ on TOP "SPK_OUT7+_L01_P1411" (solid, pour order 1411): 17785,14180 18009.42,14180 18026.98,14162.44 18026.98,14071.98 18005,14050 17785,14050 17760,14075 17760,14155
SPK_OUT7- on TOP "SPK_OUT7-_L01_P1410" (solid, pour order 1410): 17390,14185 17614.42,14185 17631.98,14167.44 17631.98,14076.98 17610,14055 17390,14055 17365,14080 17365,14160
SPK_OUT6- on TOP "SPK_OUT6-_L01_P1409" (solid, pour order 1409): 16710,14185 16934.42,14185 16951.98,14167.44 16951.98,14076.98 16930,14055 16710,14055 16685,14080 16685,14160
SPK_OUT3+ on TOP "SPK_OUT3+_L01_P1408" (solid, pour order 1408): 16091.06,14178.55 16326.45,14178.55 16350,14155 16350,14070 16328.55,14048.55 16091.06,14048.55 16066.06,14073.55 16066.06,14153.55
SPK_OUT3- on TOP "SPK_OUT3-_L01_P1407" (solid, pour order 1407): 15695,14180 15919.42,14180 15936.98,14162.44 15936.98,14071.98 15915,14050 15695,14050 15670,14075 15670,14155
SPK_OUT2- on TOP "SPK_OUT2-_L01_P1406" (solid, pour order 1406): 15025,14185 15249.42,14185 15266.98,14167.44 15266.98,14076.98 15245,14055 15025,14055 15000,14080 15000,14160
NETC93_1 on TOP "NETC93_1_L01_P1405" (solid, pour order 1405): 17773.6,14466.71 18003.29,14466.71 18025,14445 18025,14215 18005.87,14195.87 17771.02,14195.87 17755,14211.89 17755,14448.11
NETC94_1 on TOP "NETC94_1_L01_P1404" (solid, pour order 1404): 17411.19,14476.19 17617.76,14476.19 17638.74,14455.21 17638.74,14225.49 17618.6,14205.35 17409.65,14205.35 17385,14230 17385,14450
NETC85_1 on TOP "NETC85_1_L01_P1403" (solid, pour order 1403): 17086.12,14476.63 17242.7,14476.63 17263.68,14455.65 17263.68,14225.93 17243.54,14205.79 17083.54,14205.79 17067.52,14221.81 17067.52,14458.03
NETC34_1 on TOP "NETC34_1_L01_P1398" (solid, pour order 1398): 15016.19,14476.19 15242.76,14476.19 15263.74,14455.21 15263.74,14225.49 15243.6,14205.35 15014.65,14205.35 14990,14230 14990,14450
NETC26_1 on TOP "NETC26_1_L01_P1397" (solid, pour order 1397): 14976.19,13826.19 15242.76,13826.19 15263.74,13805.21 15263.74,13575.49 15243.6,13555.35 14974.65,13555.35 14950,13580 14950,13800
NETC25_1 on TOP "NETC25_1_L01_P1396" (solid, pour order 1396): 15406.18,13826.19 15658.81,13826.19 15685,13800 15685,13585 15672.36,13572.36 15407.64,13572.36 15387.58,13592.42 15387.58,13807.59
NETC49_1 on TOP "NETC49_1_L01_P1395" (solid, pour order 1395): 16087.58,13825.84 16244.16,13825.84 16265.14,13804.86 16265.14,13575.14 16245,13555 16085,13555 16068.98,13571.02 16068.98,13807.24
NETC46_1 on TOP "NETC46_1_L01_P1381" (solid, pour order 1381): 15742.9,14023.82 16021.74,14023.82 16039.3,14006.25 16039.3,13895.22 16017.9,13873.82 15746.74,13873.82 15724.3,13896.25 15724.3,14005.22
NETC50_1 on TOP "NETC50_1_L01_P1345" (solid, pour order 1345): 15760.84,13835.84 15924.16,13835.84 15945.14,13814.86 15945.14,13585.14 15925,13565 15745,13565 15730,13580 15730,13805
NETC98_1 on TOP "NETC98_1_L01_P1377" (solid, pour order 1377): 17459.76,14032.16 17698.21,14032.16 17714.17,14016.2 17714.17,13897.18 17699.16,13882.16 17463.59,13882.16 17441.16,13904.6 17441.16,14013.57
NETC81_2 on TOP "NETC81_2_L01_P1374" (solid, pour order 1374): 17066.07,14675.47 17314.53,14675.47 17335,14655 17335,14545 17315.47,14525.47 17069.9,14525.47 17047.47,14547.91 17047.47,14656.88
PVDD_2 on TOP "PVDD_2_L01_P1373" (solid, pour order 1373): 17 vertices, not listed, extent 17660.11,15265 17930.89,15360.75
NETC97_2 on TOP "NETC97_2_L01_P1372" (solid, pour order 1372): 17722.57,15274.8 17717.57,15269.8 17652.57,15269.8 17632.57,15249.8 17577.57,15249.8 17567.57,15259.8 17567.57,15314.8 17577.57,15324.8 17632.57,15324.8 17642.57,15314.8 17642.57,15294.8 17647.57,15289.8 17717.57,15289.8 17722.57,15284.8
GND on TOP "GND_L01_P1371" (solid, pour order 1371): 19 vertices, not listed, extent 17658.83,15075.6 17933.84,15249.15
PVDD_2 on TOP "PVDD_2_L01_P1370" (solid, pour order 1370): 17665.06,15069.54 17815.84,15069.54 17828.8,15056.58 17828.8,15038.48 17843.8,15023.48 17918.8,15023.48 17933.8,15008.48 17933.8,14933.48 17898.8,14898.48 17748.8,14898.48 17688.8,14958.48 17620.07,14958.48 17614.6,14963.95 17614.6,15020.02 17664.13,15069.55
NETC98_1 on TOP "NETC98_1_L01_P1369" (solid, pour order 1369): 17721.43,15086.34 17716.43,15081.34 17651.43,15081.34 17631.43,15061.34 17576.43,15061.34 17566.43,15071.34 17566.43,15126.34 17576.43,15136.34 17631.43,15136.34 17641.43,15126.34 17641.43,15106.34 17646.43,15101.34 17716.43,15101.34 17721.43,15096.34
NETC89_2 on TOP "NETC89_2_L01_P1368" (solid, pour order 1368): 20 vertices, not listed, extent 17580.75,14519.77 17960.75,15024.77
GND on TOP "GND_L01_P1367" (solid, pour order 1367): 17486.88,15020.61 17488.23,15021.95 17538.34,15021.95 17541.88,15018.41 17541.88,14963.41 17541.88,14953.41 17561.88,14933.41 17576.77,14933.41 17591.88,14918.3 17591.88,14733.41 17581.88,14723.41 17496.88,14723.41 17486.88,14733.41
NETC90_1 on TOP "NETC90_1_L01_P1366" (solid, pour order 1366): 17465.08,15119.92 17472.12,15112.88 17472.12,15045.06 17446.61,15028.02 17446.61,14963.24 17444.69,14961.32 17424.8,14961.32 17422.27,14963.85 17422.27,15031.86 17400,15054.12 17400,15106.93 17412.99,15119.92
PVDD_2 on TOP "PVDD_2_L01_P1365" (solid, pour order 1365): 17364.1,15025.94 17409.1,15025.94 17414.65,15020.39 17414.65,14960.39 17424.1,14950.94 17469.1,14950.94 17479.1,14940.94 17479.1,14775.94 17459.1,14755.94 17334.1,14755.94 17314.1,14775.94 17314.1,14935.94 17329.1,14950.94 17359.1,14950.94 17359.1,15020.94
GND on TOP "GND_L01_P1364" (solid, pour order 1364): 17234.59,15023.85 17235.93,15025.19 17286.04,15025.19 17289.59,15021.65 17289.59,14951.65 17304.59,14936.65 17304.59,14816.65 17294.59,14806.65 17244.59,14806.65 17234.59,14816.65
NETC81_2 on TOP "NETC81_2_L01_P1363" (solid, pour order 1363): 17375,15120 17385,15110 17385,15050.02 17352.19,15028.1 17352.19,14963.32 17350.26,14961.4 17330.37,14961.4 17327.84,14963.93 17327.84,15031.94 17308.76,15051.03 17308.76,15110.19 17318.57,15120
NETC82_1 on TOP "NETC82_1_L01_P1362" (solid, remove dead copper, pour order 1362): 29 vertices, not listed, extent 16774.26,14522.81 17229.26,15022.81
NETC74_1 on TOP "NETC74_1_L01_P1361" (solid, pour order 1361): 17053.53,15286.52 17058.53,15291.52 17118.53,15291.52 17128.53,15301.52 17128.53,15341.52 17138.53,15351.52 17198.53,15351.52 17208.53,15341.52 17208.53,15276.52 17198.53,15266.52 17058.53,15266.52 17053.53,15271.52
NETC71_2 on TOP "NETC71_2_L01_P1360" (solid, pour order 1360): 17050,15095 17055,15100 17120,15100 17140,15120 17195,15120 17205,15110 17205,15055 17195,15045 17140,15045 17130,15055 17130,15075 17125,15080 17055,15080 17050,15085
